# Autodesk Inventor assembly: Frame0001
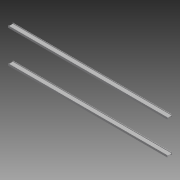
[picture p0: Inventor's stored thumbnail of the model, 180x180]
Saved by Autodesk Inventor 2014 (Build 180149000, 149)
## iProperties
Created: 2009-11
Part Number: Frame0001
Document SubType Name: Assembly
Designer: pokornp
_FrameDoc: Frame Assembly
_Version: 15.0.0
Author: pokornp
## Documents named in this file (4)
- C:\Users\iTools\Desktop\tutorial files\Frame Analysis 1\asm\Frame\Frame0001.iam
- C:\Users\iTools\Desktop\tutorial files\Frame Analysis 1\asm\Frame\Skeleton0001.ipt
- C:\Users\iTools\Desktop\tutorial files\Frame Analysis 1\asm\Frame\DIN I 300 00000001.ipt
- C:\Users\iTools\Desktop\tutorial files\Frame Analysis 1\asm\Frame\DIN I 300 00000002.ipt
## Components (3 placed, 3 different names)
1. Frame Reference Model
2. DIN I 300 00000001:1
3. DIN I 300 00000002:1
